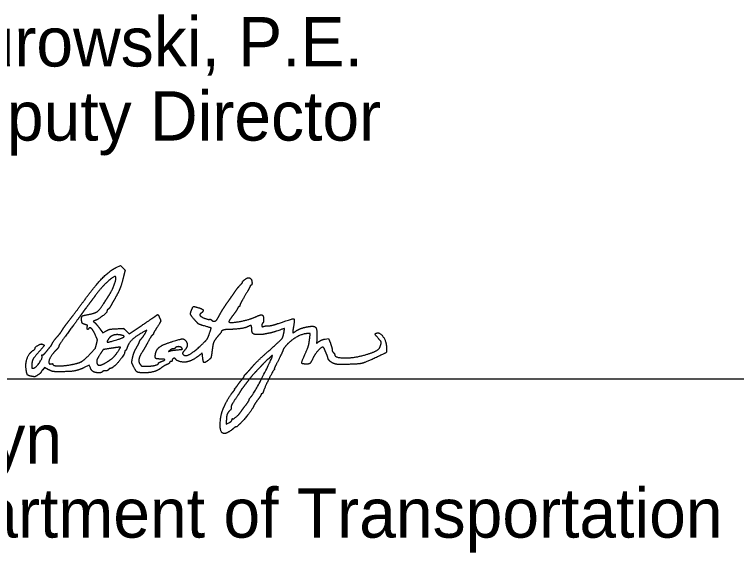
# Model space of a CAD drawing. Extents: x 0 to 34, y 0 to 22.
# Drawn here: x 25.697 to 27.744, y 7.199 to 8.723 of the extents above; entities that cross this region are included whole.
import ezdxf

# ---------------------------------------------------------------- set-up
doc = ezdxf.new("R2010")
doc.units = 0
doc.layers.add('SH_Data', color=7, linetype='Continuous')
doc.layers.add('SH_Text', color=7, linetype='Continuous')

msp = doc.modelspace()

# ---------------------------------------------------------------- linework, layer by layer
at = {"layer": 'SH_Data'}
msp.add_line((24.5, 7.691), (28, 7.691), dxfattribs=at)
at = {"layer": 'SH_Text'}
for points in [[(25.9853, 8.0062), (25.9979, 8.012), (26.0042, 8.0057), (26.0106, 7.9993), (26.0062, 7.9806)], [(25.9253, 7.8562), (25.9203, 7.8546), (25.9255, 7.8495)], [(26.0143, 7.8265), (26.0224, 7.8189), (26.0587, 7.843)], [(25.9392, 7.8328), (25.9477, 7.8213), (25.9565, 7.8265)], [(26.0682, 7.8212), (26.0726, 7.8292), (26.0671, 7.8263)], [(26.534, 7.8053), (26.5355, 7.8191), (26.5277, 7.8191)], [(26.5779, 7.8037), (26.5876, 7.8053), (26.5926, 7.7917)], [(26.23, 7.7576), (26.2293, 7.7644), (26.2234, 7.7593)], [(25.7937, 7.7169), (25.7822, 7.7227), (25.7771, 7.7169)], [(25.9123, 7.722), (25.909, 7.73), (25.8951, 7.7231)], [(26.2977, 7.5714), (26.2977, 7.5621), (26.3052, 7.5664)]]:
    msp.add_lwpolyline(points, dxfattribs=at)
for points in [[(25.8957, 7.9143), (25.9254, 7.9549), (25.9672, 7.9978), (25.9853, 8.0062)], [(25.9838, 7.9804), (25.9802, 7.984), (25.9416, 7.9483), (25.9262, 7.927)], [(25.9655, 7.9283), (25.9749, 7.9432), (25.9869, 7.9773), (25.9838, 7.9804)], [(26.0062, 7.9806), (26.0012, 7.9595), (25.992, 7.9359), (25.9826, 7.9199)], [(26.3367, 7.9562), (26.3403, 7.9598), (26.3433, 7.9634), (26.3433, 7.9643)], [(26.3433, 7.9643), (26.3433, 7.9671), (26.3565, 7.9774), (26.3602, 7.9775)], [(26.3602, 7.9775), (26.3623, 7.9775), (26.3652, 7.9762), (26.3668, 7.9747)], [(26.3668, 7.9747), (26.3703, 7.9712), (26.3707, 7.9559), (26.3673, 7.9559)], [(26.3229, 7.9389), (26.3269, 7.9448), (26.3331, 7.9525), (26.3367, 7.9562)], [(26.3649, 7.9534), (26.3649, 7.952), (26.3584, 7.9399), (26.3505, 7.9266)], [(26.3673, 7.9559), (26.366, 7.9559), (26.3649, 7.9548), (26.3649, 7.9534)], [(25.9262, 7.927), (25.9226, 7.9221), (25.9132, 7.9094), (25.9053, 7.8989)], [(25.955, 7.9117), (25.9583, 7.9169), (25.963, 7.9244), (25.9655, 7.9283)], [(26.3013, 7.9079), (26.3092, 7.9192), (26.319, 7.9331), (26.3229, 7.9389)], [(26.3505, 7.9266), (26.3426, 7.9132), (26.3361, 7.9008), (26.3361, 7.8991)], [(25.8555, 7.8609), (25.8644, 7.8722), (25.8825, 7.8963), (25.8957, 7.9143)], [(25.9052, 7.873), (25.9258, 7.8768), (25.9398, 7.8877), (25.955, 7.9117)], [(25.9826, 7.9199), (25.9791, 7.914), (25.9739, 7.9048), (25.971, 7.8995)], [(26.2799, 7.8743), (26.2837, 7.8816), (26.2933, 7.8967), (26.3013, 7.9079)], [(25.9053, 7.8989), (25.8974, 7.8884), (25.8893, 7.8774), (25.8873, 7.8745)], [(25.9593, 7.8826), (25.9593, 7.8788), (25.9335, 7.8588), (25.9253, 7.8562)], [(25.9626, 7.888), (25.9608, 7.887), (25.9593, 7.8845), (25.9593, 7.8826)], [(25.971, 7.8995), (25.9682, 7.8943), (25.9644, 7.8891), (25.9626, 7.888)], [(26.209, 7.8568), (26.1975, 7.8698), (26.1953, 7.8766), (26.1992, 7.8862)], [(26.1992, 7.8862), (26.203, 7.8952), (26.2061, 7.8963), (26.2188, 7.8925)], [(26.2188, 7.8925), (26.2308, 7.889), (26.2337, 7.8828), (26.226, 7.8769)], [(26.3288, 7.8893), (26.3271, 7.8857), (26.3209, 7.8766), (26.3152, 7.8691)], [(26.3341, 7.8959), (26.333, 7.8959), (26.3306, 7.893), (26.3288, 7.8893)], [(26.3361, 7.8991), (26.3361, 7.8973), (26.3352, 7.8959), (26.3341, 7.8959)], [(25.8873, 7.8745), (25.8853, 7.8715), (25.87, 7.8506), (25.8532, 7.8279)], [(25.8873, 7.8609), (25.8873, 7.8677), (25.8914, 7.8705), (25.9052, 7.873)], [(26.0587, 7.843), (26.0786, 7.8563), (26.0962, 7.8682), (26.0978, 7.8695)], [(26.0978, 7.8695), (26.1023, 7.8733), (26.1047, 7.8724), (26.1077, 7.8658)], [(26.1077, 7.8658), (26.1121, 7.8562), (26.1111, 7.8521), (26.1009, 7.8362)], [(26.226, 7.8769), (26.2233, 7.8749), (26.2218, 7.872), (26.2228, 7.8707)], [(26.2228, 7.8707), (26.2254, 7.8669), (26.2453, 7.8587), (26.25, 7.8595)], [(26.2706, 7.8581), (26.2719, 7.8598), (26.2761, 7.8671), (26.2799, 7.8743)], [(26.3152, 7.8691), (26.3096, 7.8617), (26.3049, 7.8544), (26.3049, 7.8531)], [(26.3049, 7.8531), (26.3049, 7.8478), (26.3645, 7.8587), (26.3825, 7.8673)], [(26.3825, 7.8673), (26.3955, 7.8735), (26.4033, 7.8703), (26.4033, 7.8589)], [(25.834, 7.8315), (25.837, 7.8363), (25.8467, 7.8495), (25.8555, 7.8609)], [(25.8983, 7.8445), (25.8911, 7.8463), (25.8873, 7.852), (25.8873, 7.8609)], [(25.9034, 7.8382), (25.9043, 7.8418), (25.9031, 7.8433), (25.8983, 7.8445)], [(25.9255, 7.8495), (25.9283, 7.8467), (25.9345, 7.8392), (25.9392, 7.8328)], [(26.2325, 7.8416), (26.2217, 7.8447), (26.2168, 7.8479), (26.209, 7.8568)], [(26.2493, 7.8179), (26.255, 7.8347), (26.2546, 7.8353), (26.2325, 7.8416)], [(26.25, 7.8595), (26.2522, 7.8599), (26.2548, 7.859), (26.2556, 7.8577)], [(26.2556, 7.8577), (26.2578, 7.8542), (26.2678, 7.8545), (26.2706, 7.8581)], [(26.3697, 7.8338), (26.3697, 7.8411), (26.366, 7.8427), (26.3583, 7.8385)], [(26.4009, 7.8491), (26.3996, 7.8483), (26.3985, 7.8455), (26.3985, 7.8428)], [(26.3985, 7.8428), (26.3985, 7.8389), (26.3995, 7.8383), (26.4039, 7.8397)], [(26.4033, 7.8589), (26.4033, 7.8544), (26.4022, 7.85), (26.4009, 7.8491)], [(26.4168, 7.8412), (26.421, 7.841), (26.4339, 7.8442), (26.4456, 7.8482)], [(26.4456, 7.8482), (26.486, 7.8621), (26.4919, 7.8605), (26.4878, 7.8366)], [(25.8177, 7.8096), (25.8243, 7.8169), (25.8285, 7.8227), (25.834, 7.8315)], [(25.8532, 7.8279), (25.8364, 7.8053), (25.8226, 7.7851), (25.8225, 7.7831)], [(25.9077, 7.8335), (25.9052, 7.8296), (25.902, 7.8331), (25.9034, 7.8382)], [(25.9265, 7.8149), (25.9203, 7.8285), (25.9106, 7.8382), (25.9077, 7.8335)], [(25.9565, 7.8265), (25.963, 7.8304), (25.9706, 7.8321), (25.9857, 7.8329)], [(25.9857, 7.8329), (26.006, 7.8341), (26.0062, 7.8341), (26.0143, 7.8265)], [(26.0671, 7.8263), (26.0437, 7.8137), (26.021, 7.793), (26.0168, 7.7806)], [(26.0554, 7.8031), (26.0608, 7.8091), (26.0633, 7.8127), (26.0682, 7.8212)], [(26.1009, 7.8362), (26.0956, 7.8281), (26.0913, 7.8205), (26.0913, 7.8194)], [(26.2833, 7.824), (26.2833, 7.8231), (26.2791, 7.8177), (26.2739, 7.8119)], [(26.3075, 7.8311), (26.296, 7.8311), (26.2833, 7.8274), (26.2833, 7.824)], [(26.3583, 7.8385), (26.3527, 7.8355), (26.3225, 7.8311), (26.3075, 7.8311)], [(26.389, 7.8162), (26.3766, 7.8162), (26.3697, 7.8225), (26.3697, 7.8338)], [(26.4039, 7.8397), (26.4069, 7.8407), (26.4127, 7.8413), (26.4168, 7.8412)], [(26.4161, 7.7686), (26.4516, 7.8002), (26.4585, 7.8083), (26.4609, 7.8216)], [(26.4403, 7.8262), (26.4325, 7.8235), (26.4229, 7.8208), (26.4189, 7.8202)], [(26.4609, 7.8216), (26.463, 7.8331), (26.4613, 7.8335), (26.4403, 7.8262)], [(26.4878, 7.8366), (26.4865, 7.829), (26.4857, 7.8224), (26.4862, 7.8219)], [(26.4862, 7.8219), (26.4867, 7.8214), (26.4901, 7.8231), (26.4938, 7.8257)], [(26.4938, 7.8257), (26.501, 7.8308), (26.5192, 7.8371), (26.5329, 7.8393)], [(26.5329, 7.8393), (26.5476, 7.8416), (26.5552, 7.8311), (26.5544, 7.8099)], [(26.7236, 7.8206), (26.7322, 7.8239), (26.7506, 7.799), (26.7516, 7.7827)], [(25.8033, 7.7891), (25.8033, 7.7908), (25.8124, 7.8038), (25.8177, 7.8096)], [(25.9298, 7.7903), (25.9323, 7.8002), (25.932, 7.8024), (25.9265, 7.8149)], [(25.9649, 7.8057), (25.9579, 7.795), (25.9625, 7.7942), (25.9869, 7.8017)], [(25.9975, 7.8152), (25.9866, 7.8174), (25.9693, 7.8123), (25.9649, 7.8057)], [(25.9869, 7.8017), (26.0061, 7.8076), (26.0101, 7.8127), (25.9975, 7.8152)], [(26.0514, 7.7961), (26.0517, 7.7978), (26.0535, 7.801), (26.0554, 7.8031)], [(26.0809, 7.8051), (26.0727, 7.7897), (26.0649, 7.7759), (26.0588, 7.7662)], [(26.0877, 7.8144), (26.0858, 7.8128), (26.0827, 7.8086), (26.0809, 7.8051)], [(26.0913, 7.8194), (26.0913, 7.8182), (26.0897, 7.816), (26.0877, 7.8144)], [(26.1347, 7.7934), (26.1665, 7.804), (26.1799, 7.8044), (26.185, 7.7949)], [(26.231, 7.7906), (26.2414, 7.8006), (26.2455, 7.8068), (26.2493, 7.8179)], [(26.2739, 7.8119), (26.2655, 7.8024), (26.2597, 7.7899), (26.2581, 7.7771)], [(26.4057, 7.8176), (26.4024, 7.8168), (26.3949, 7.8162), (26.389, 7.8162)], [(26.4189, 7.8202), (26.4149, 7.8195), (26.409, 7.8184), (26.4057, 7.8176)], [(26.5277, 7.8191), (26.515, 7.8191), (26.4812, 7.8007), (26.4691, 7.7872)], [(26.5194, 7.7575), (26.5284, 7.7774), (26.5324, 7.7906), (26.534, 7.8053)], [(26.5544, 7.8099), (26.5537, 7.7915), (26.5536, 7.7918), (26.5613, 7.7973)], [(26.5613, 7.7973), (26.5651, 7.8), (26.5726, 7.8029), (26.5779, 7.8037)], [(26.7245, 7.8105), (26.7192, 7.8162), (26.719, 7.8189), (26.7236, 7.8206)], [(26.7336, 7.7814), (26.7376, 7.7932), (26.736, 7.7981), (26.7245, 7.8105)], [(25.7553, 7.7771), (25.7554, 7.7809), (25.7721, 7.7908), (25.7759, 7.7894)], [(25.7759, 7.7894), (25.7819, 7.7871), (25.7796, 7.7822), (25.7653, 7.7663)], [(25.7888, 7.7699), (25.7941, 7.7765), (25.7996, 7.7832), (25.8009, 7.7848)], [(25.8009, 7.7848), (25.8022, 7.7864), (25.8033, 7.7884), (25.8033, 7.7891)], [(25.8225, 7.7831), (25.8224, 7.7812), (25.8191, 7.7763), (25.8151, 7.7724)], [(25.9101, 7.7598), (25.9262, 7.7774), (25.9265, 7.7779), (25.9298, 7.7903)], [(25.9901, 7.7679), (25.9979, 7.7793), (25.997, 7.7814), (25.9851, 7.7796)], [(26.0168, 7.7806), (26.0151, 7.7754), (26.0128, 7.7711), (26.0117, 7.7711)], [(26.0429, 7.779), (26.0473, 7.7867), (26.0512, 7.7943), (26.0514, 7.7961)], [(26.0971, 7.7623), (26.0992, 7.7736), (26.1154, 7.787), (26.1347, 7.7934)], [(26.1708, 7.7792), (26.168, 7.7825), (26.1546, 7.7817), (26.1523, 7.7781)], [(26.174, 7.7617), (26.1793, 7.7531), (26.2061, 7.7666), (26.231, 7.7906)], [(26.185, 7.7949), (26.1882, 7.7889), (26.1848, 7.7775), (26.1774, 7.7696)], [(26.4691, 7.7872), (26.4632, 7.7807), (26.4585, 7.7741), (26.4585, 7.7726)], [(26.5709, 7.7807), (26.5666, 7.7807), (26.5483, 7.7602), (26.5436, 7.7501)], [(26.5765, 7.7741), (26.575, 7.7778), (26.5725, 7.7807), (26.5709, 7.7807)], [(26.5926, 7.7917), (26.5954, 7.7843), (26.5977, 7.7761), (26.5977, 7.7736)], [(26.6847, 7.7571), (26.7084, 7.7634), (26.7314, 7.7748), (26.7336, 7.7814)], [(26.7516, 7.7827), (26.7526, 7.7674), (26.7499, 7.7643), (26.7265, 7.7533)], [(25.7304, 7.7155), (25.7275, 7.734), (25.7382, 7.764), (25.7506, 7.7718)], [(25.7653, 7.7663), (25.7516, 7.7511), (25.7466, 7.741), (25.746, 7.7272)], [(25.7506, 7.7718), (25.7532, 7.7734), (25.7553, 7.7758), (25.7553, 7.7771)], [(25.7765, 7.7586), (25.7779, 7.7583), (25.7834, 7.7633), (25.7888, 7.7699)], [(25.8151, 7.7724), (25.8053, 7.7628), (25.7929, 7.7407), (25.7947, 7.736)], [(25.8536, 7.7305), (25.8763, 7.7342), (25.8959, 7.7444), (25.9101, 7.7598)], [(25.9406, 7.762), (25.9324, 7.7493), (25.9292, 7.7395), (25.9315, 7.7337)], [(25.9677, 7.7769), (25.9499, 7.7743), (25.9479, 7.7732), (25.9406, 7.762)], [(25.9602, 7.7392), (25.9714, 7.7462), (25.9824, 7.7567), (25.9901, 7.7679)], [(25.9851, 7.7796), (25.9795, 7.7787), (25.9717, 7.7775), (25.9677, 7.7769)], [(26.0097, 7.7681), (26.0095, 7.7596), (25.9764, 7.7207), (25.9693, 7.7207)], [(26.0117, 7.7711), (26.0106, 7.7711), (26.0097, 7.7698), (26.0097, 7.7681)], [(26.032, 7.7512), (26.0336, 7.7589), (26.0385, 7.7714), (26.0429, 7.779)], [(26.0588, 7.7662), (26.0508, 7.7536), (26.0486, 7.7384), (26.0537, 7.7316)], [(26.1106, 7.7471), (26.0991, 7.7471), (26.0951, 7.7517), (26.0971, 7.7623)], [(26.138, 7.7721), (26.1334, 7.7684), (26.1334, 7.7684), (26.1381, 7.77)], [(26.1468, 7.7759), (26.1445, 7.7759), (26.1405, 7.7742), (26.138, 7.7721)], [(26.1381, 7.77), (26.1407, 7.771), (26.1483, 7.7722), (26.1549, 7.7728)], [(26.1523, 7.7781), (26.1516, 7.7769), (26.1491, 7.7759), (26.1468, 7.7759)], [(26.1549, 7.7728), (26.1716, 7.7743), (26.174, 7.7753), (26.1708, 7.7792)], [(26.1774, 7.7696), (26.1746, 7.7667), (26.1731, 7.7631), (26.174, 7.7617)], [(26.2581, 7.7771), (26.2553, 7.7546), (26.2536, 7.7492), (26.2479, 7.7447)], [(26.372, 7.7259), (26.3792, 7.7343), (26.399, 7.7535), (26.4161, 7.7686)], [(26.4585, 7.7726), (26.4585, 7.771), (26.4525, 7.7581), (26.4453, 7.744)], [(26.5824, 7.76), (26.5806, 7.7641), (26.578, 7.7705), (26.5765, 7.7741)], [(26.5858, 7.7504), (26.5857, 7.7515), (26.5842, 7.7558), (26.5824, 7.76)], [(26.5977, 7.7736), (26.5977, 7.7711), (26.5993, 7.7675), (26.6013, 7.7655)], [(26.6013, 7.7655), (26.6033, 7.7635), (26.6049, 7.7608), (26.6049, 7.7595)], [(26.6049, 7.7595), (26.6049, 7.7509), (26.6555, 7.7495), (26.6847, 7.7571)], [(25.7509, 7.7212), (25.7572, 7.7221), (25.7773, 7.7505), (25.7753, 7.7557)], [(25.7753, 7.7557), (25.7745, 7.7577), (25.7751, 7.759), (25.7765, 7.7586)], [(25.9315, 7.7337), (25.9335, 7.7284), (25.9471, 7.731), (25.9602, 7.7392)], [(26.034, 7.7272), (26.0296, 7.7363), (26.0294, 7.7385), (26.032, 7.7512)], [(26.1057, 7.7354), (26.1057, 7.7364), (26.1094, 7.7386), (26.114, 7.7402)], [(26.114, 7.7402), (26.1243, 7.7439), (26.1227, 7.7471), (26.1106, 7.7471)], [(26.1405, 7.7399), (26.1385, 7.7399), (26.1369, 7.7388), (26.1369, 7.7375)], [(26.1441, 7.7433), (26.1441, 7.7414), (26.1425, 7.7399), (26.1405, 7.7399)], [(26.1536, 7.7473), (26.1516, 7.7506), (26.1441, 7.7474), (26.1441, 7.7433)], [(26.1849, 7.7388), (26.1763, 7.7372), (26.1565, 7.7426), (26.1536, 7.7473)], [(26.2234, 7.7593), (26.214, 7.7511), (26.194, 7.7405), (26.1849, 7.7388)], [(26.2479, 7.7447), (26.2362, 7.7355), (26.2318, 7.7386), (26.23, 7.7576)], [(26.3694, 7.6421), (26.3771, 7.6508), (26.4303, 7.7545), (26.4282, 7.7566)], [(26.4079, 7.7393), (26.4038, 7.735), (26.3933, 7.724), (26.3845, 7.7147)], [(26.4167, 7.7471), (26.416, 7.7471), (26.412, 7.7436), (26.4079, 7.7393)], [(26.4225, 7.7525), (26.4201, 7.7496), (26.4175, 7.7471), (26.4167, 7.7471)], [(26.4282, 7.7566), (26.4275, 7.7573), (26.4249, 7.7555), (26.4225, 7.7525)], [(26.4453, 7.744), (26.438, 7.7299), (26.4329, 7.7183), (26.4339, 7.7183)], [(26.5267, 7.7327), (26.5122, 7.7327), (26.5106, 7.7382), (26.5194, 7.7575)], [(26.5436, 7.7501), (26.5379, 7.7377), (26.5331, 7.7327), (26.5267, 7.7327)], [(26.6014, 7.7348), (26.5944, 7.7381), (26.5859, 7.7465), (26.5858, 7.7504)], [(26.7265, 7.7533), (26.6917, 7.737), (26.6707, 7.7322), (26.6313, 7.7318)], [(25.746, 7.7272), (25.7458, 7.7216), (25.7466, 7.7205), (25.7509, 7.7212)], [(25.7947, 7.736), (25.7956, 7.7336), (25.7979, 7.7327), (25.8009, 7.7334)], [(25.8009, 7.7334), (25.8035, 7.7341), (25.8057, 7.7338), (25.8057, 7.7327)], [(25.8057, 7.7327), (25.8057, 7.7281), (25.8313, 7.7269), (25.8536, 7.7305)], [(25.8951, 7.7231), (25.8796, 7.7154), (25.8544, 7.7111), (25.8245, 7.7111)], [(25.9205, 7.7113), (25.9179, 7.7128), (25.9142, 7.7175), (25.9123, 7.722)], [(25.9693, 7.7207), (25.9681, 7.7207), (25.9657, 7.7191), (25.9641, 7.7171)], [(26.0658, 7.708), (26.0483, 7.7081), (26.0413, 7.7123), (26.034, 7.7272)], [(26.0537, 7.7316), (26.0566, 7.7277), (26.0601, 7.7268), (26.0713, 7.7268)], [(26.1123, 7.7212), (26.1046, 7.7149), (26.0803, 7.7079), (26.0658, 7.708)], [(26.0713, 7.7268), (26.0853, 7.7267), (26.1057, 7.7318), (26.1057, 7.7354)], [(26.1315, 7.7326), (26.1242, 7.7293), (26.1165, 7.7247), (26.1123, 7.7212)], [(26.1369, 7.7375), (26.1369, 7.7361), (26.1345, 7.7339), (26.1315, 7.7326)], [(26.3535, 7.7055), (26.3565, 7.7083), (26.3648, 7.7175), (26.372, 7.7259)], [(26.6313, 7.7318), (26.6164, 7.7316), (26.6061, 7.7326), (26.6014, 7.7348)], [(25.747, 7.6978), (25.7361, 7.6998), (25.7323, 7.7039), (25.7304, 7.7155)], [(25.7637, 7.7019), (25.7572, 7.6974), (25.7536, 7.6965), (25.747, 7.6978)], [(25.7721, 7.7093), (25.7721, 7.7083), (25.7683, 7.705), (25.7637, 7.7019)], [(25.7771, 7.7169), (25.7744, 7.7137), (25.7721, 7.7103), (25.7721, 7.7093)], [(25.8245, 7.7111), (25.8089, 7.7111), (25.803, 7.7122), (25.7937, 7.7169)], [(25.9461, 7.7111), (25.9441, 7.7079), (25.9266, 7.7081), (25.9205, 7.7113)], [(25.9543, 7.7135), (25.9506, 7.7135), (25.9469, 7.7125), (25.9461, 7.7111)], [(25.9641, 7.7171), (25.9625, 7.7152), (25.9581, 7.7135), (25.9543, 7.7135)], [(26.3415, 7.6884), (26.3451, 7.6927), (26.3481, 7.6971), (26.3481, 7.6983)], [(26.3481, 7.6983), (26.3482, 7.6994), (26.3506, 7.7027), (26.3535, 7.7055)], [(26.3845, 7.7147), (26.3757, 7.7054), (26.3658, 7.6942), (26.3625, 7.6897)], [(26.4331, 7.7165), (26.4304, 7.7147), (26.4052, 7.6637), (26.4022, 7.6541)], [(26.4339, 7.7183), (26.4349, 7.7183), (26.4345, 7.7175), (26.4331, 7.7165)], [(26.3313, 7.6751), (26.3333, 7.6782), (26.3379, 7.6842), (26.3415, 7.6884)], [(26.3625, 7.6897), (26.3544, 7.6788), (26.3439, 7.665), (26.3409, 7.6614)], [(26.3176, 7.6553), (26.3203, 7.6583), (26.3218, 7.6607), (26.3209, 7.6607)], [(26.3209, 7.6607), (26.32, 7.6607), (26.3212, 7.6627), (26.3235, 7.6651)], [(26.3235, 7.6651), (26.3258, 7.6676), (26.3293, 7.6721), (26.3313, 7.6751)], [(26.3385, 7.6576), (26.3385, 7.657), (26.3322, 7.6471), (26.3244, 7.6354)], [(26.3409, 7.6614), (26.3396, 7.6598), (26.3385, 7.6581), (26.3385, 7.6576)], [(26.2875, 7.6027), (26.2934, 7.6176), (26.3105, 7.6475), (26.3176, 7.6553)], [(26.3625, 7.6318), (26.3625, 7.6331), (26.3656, 7.6377), (26.3694, 7.6421)], [(26.3961, 7.6462), (26.3961, 7.6449), (26.3918, 7.6381), (26.3866, 7.6312)], [(26.3983, 7.6487), (26.3971, 7.6487), (26.3961, 7.6476), (26.3961, 7.6462)], [(26.4022, 7.6541), (26.4013, 7.6512), (26.3996, 7.6487), (26.3983, 7.6487)], [(26.3244, 7.6354), (26.3158, 7.6224), (26.3108, 7.6126), (26.3115, 7.6099)], [(26.3523, 7.6159), (26.3579, 7.6233), (26.3625, 7.6304), (26.3625, 7.6318)], [(26.3866, 7.6312), (26.3814, 7.6243), (26.3763, 7.6163), (26.3752, 7.6135)], [(26.2857, 7.5383), (26.2798, 7.5421), (26.281, 7.5864), (26.2875, 7.6027)], [(26.3078, 7.6013), (26.3019, 7.5961), (26.2977, 7.5838), (26.2977, 7.5714)], [(26.3115, 7.6099), (26.3122, 7.6074), (26.3106, 7.6038), (26.3078, 7.6013)], [(26.3169, 7.5779), (26.3188, 7.5768), (26.3355, 7.5919), (26.3397, 7.5987)], [(26.3752, 7.6135), (26.3716, 7.6036), (26.3304, 7.5551), (26.3257, 7.5551)], [(26.3397, 7.5987), (26.341, 7.6008), (26.3467, 7.6086), (26.3523, 7.6159)], [(26.3139, 7.5749), (26.3145, 7.5772), (26.3159, 7.5786), (26.3169, 7.5779)], [(26.3052, 7.5664), (26.3094, 7.5688), (26.3133, 7.5726), (26.3139, 7.5749)], [(26.3257, 7.5551), (26.3243, 7.5551), (26.321, 7.5531), (26.3183, 7.5506)], [(26.2922, 7.536), (26.2906, 7.536), (26.2877, 7.537), (26.2857, 7.5383)], [(26.3183, 7.5506), (26.3121, 7.5449), (26.2961, 7.5359), (26.2922, 7.536)]]:
    msp.add_open_spline(points, degree=2, dxfattribs=at)

# ---------------------------------------------------------------- texts
for s, p in [('Anthony C. Turowski, P.E.', (24.5, 8.576)), ('District       Deputy Director', (24.5, 8.366)), ('Pamela Boratyn', (24.5, 7.451)), ('Director, Department of Transportation', (24.5, 7.241))]:
    msp.add_text(s, height=0.14, dxfattribs=at).set_placement(p)

doc.saveas('drawing.dxf')
